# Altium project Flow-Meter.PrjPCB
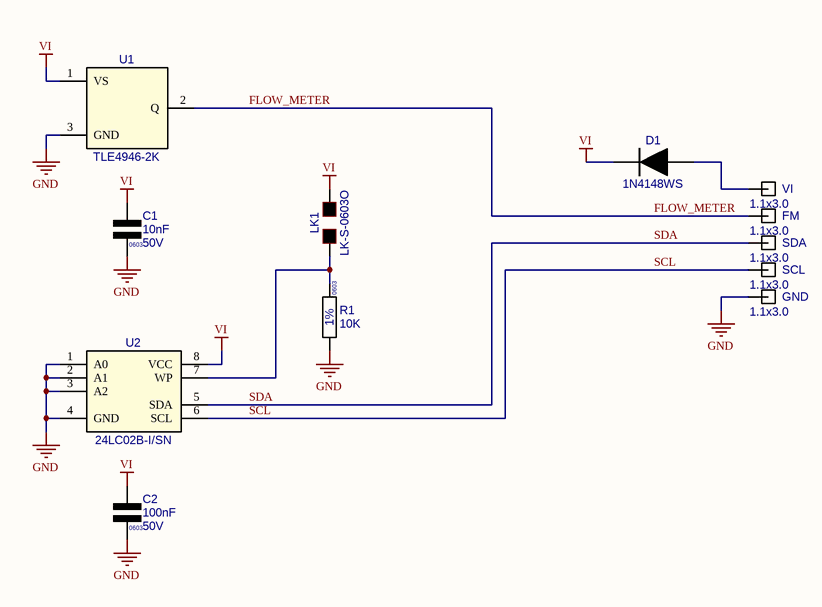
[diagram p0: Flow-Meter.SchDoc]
Version: 01.00; SCH_Title: Flow Meter; SCH_SheetTotal: 1; SCH_Reviewed: DG; SCH_QA: -; SCH_Number: NA; SCH_FILENAME: Flow-Meter.SCH; SCH_ECR: -; SCH_DRAWN: DG; SCH_DocRev: 01; SCH_Date: 20/03/2013; SCH_CM: -; SCH_Approved: DG; PCB_TITLE: Flow Meter PCB; PCB_Plot File [Assy]: Flow Meter [assy]; PCB_Plot File: Agrigel; PCB_ECRNo: -; PCB_Drawn: EDM; PCB_Drawing Number: Flow-Meter; PCB_DocRevision: 01; PCB_Company Name: AGRIGEL
1 sheet, 12 parts. Net scope: global (net labels, ports and power ports of the same name join across sheets).
Board files: Flow-Meter [assy].PcbDoc, Flow-Meter [panel].PcbDoc, Flow-Meter.PcbDoc

## Sheet Flow-Meter.SchDoc: #
size A3; ApprovedBy: #; DrawnBy: #; DocumentNumber: 1; Revision: #; SheetNumber: 1; SheetTotal: 1; DocumentRevision: #; Reviewed: #; QA: #; CM: #; ECR: #; PageSetup: Record=PageOptions|CenterHorizontal=True|CenterVertical=True|PrintScale=0.97|XCorrection=1.00|YCorrection=1.00|PrintKind=1|BorderSize=5000000|LeftOffset=0|BottomOffset=0|Orientation=2|PaperLength=1000|PaperWidth=1000|Scale=100|PaperSource=7|PrintQuality=-4|MediaType=1|DitherType=10|PaperKind=A3|PrintScaleMode=1

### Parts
C1  value 10nF  Voltage: 50V  Text1: 0603  [CAPC0603X85N]  (hidden comment: 10nF_C0603_50V_10%_X7R)
C2  value 100nF  Voltage: 50V  Text1: 0603  [CAPC0603X85N]  (hidden comment: 100nF_C0603_50V_10%_X7R)
D1  1N4148WS  [SOD323]
FM  Part Number: 1.1x3.0  [PAD-SMD-1.1x3.0mm Rect]  (hidden comment: Pad-SMD-1.1x3.0mm-H_Rectangle)
GND  Part Number: 1.1x3.0  [PAD-SMD-1.1x3.0mm Rect]  (hidden comment: Pad-SMD-1.1x3.0mm-H_Rectangle)
LK1  Part Number: LK-S-0603O  [SLINK0603-O]  (hidden comment: Link-SMD-0603-Open)  (no BOM)
R1  value 10K  Tol: 1%  Text1: 0603  [RESC0603X60N]  (hidden comment: 10K_R0603_1%)
SCL  Part Number: 1.1x3.0  [PAD-SMD-1.1x3.0mm Rect]  (hidden comment: Pad-SMD-1.1x3.0mm-H_Rectangle)
SDA  Part Number: 1.1x3.0  [PAD-SMD-1.1x3.0mm Rect]  (hidden comment: Pad-SMD-1.1x3.0mm-H_Rectangle)
U1  TLE4946-2K  [SOT23]
U2  24LC02B-I/SN  [SO8]
VI  Part Number: 1.1x3.0  [PAD-SMD-1.1x3.0mm Rect]  (hidden comment: Pad-SMD-1.1x3.0mm-H_Rectangle)

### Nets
GND: C1.2 C2.2 GND.1 R1.2 U1.3(GND) U2.1(A0) U2.2(A1) U2.3(A2) U2.4(GND)
VI: C1.1 C2.1 D1.1(C) LK1.2 U1.1(VS) U2.8(VCC)
FLOW_METER: FM.1 U1.2(Q)
SCL: SCL.1 U2.6(SCL)
SDA: SDA.1 U2.5(SDA)
NetD1_2: D1.2(A) VI.1
NetLK1_1: LK1.1 R1.1 U2.7(WP)

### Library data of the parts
C1 = 10nF_0603N_50V_10%_X7R_V: Cap Ceramic X7R; Manufacturer: Various; Part Number: 10nF 0603 50V 10% X7R; Board Tech: SMD; Tol: 10%; Reutech PN: 5910-CA-0402
C2 = 100nF_0603N_50V_10%_X7R_V: Cap Ceramic X7R; Manufacturer: Various; Part Number: 100nF 0603 50V 10% X7R; Board Tech: SMD; Tol: 10%
D1 = 1N4148WS_SOD323_H: Diode Fast Switching Surface Mount; Manufacturer: Diodes; Board Tech: SMD
FM GND SCL SDA VI = Pad-SMD-1.1x3.0mm-H_Rectangle: Surface Mount Pad 1.1x3.0mm Rectangle; Manufacturer: Generic; Board Tech: SMD; Value: SMD 1.1x3.0mm Rectangle
LK1 = Link-SMD-0603-Open: Link SMD Open 0603; Manufacturer: Generic
R1 = 10K_0603_V: Resistor Chip SMD; Manufacturer: Various; Part Number: 10K 0603 1%; Watt: 100mW; EDM-PN: RES120
U1 = TLE4946-2K_SOT23: IC Hall Effect Latch; Manufacturer: Infineon; Board Tech: SMD
U2 = 24LC02B-I/SN-SO8: IC 2K I2C Serial EEPROM; Manufacturer: Microchip; Board Tech: SMD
